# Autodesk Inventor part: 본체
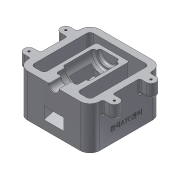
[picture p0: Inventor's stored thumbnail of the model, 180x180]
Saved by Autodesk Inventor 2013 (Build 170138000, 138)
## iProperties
Created: 2018-01
Part Number: 본체
Material: 알루미늄 6061
Document SubType Name: Modeling
Designer: Administrator
Density: 2.71 g/cm^3
Mass: 1089.46 g
Surface Area: 866.914 cm^2
Volume: 402.016 cm^3
Author: Administrator
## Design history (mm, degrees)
sketch "스케치2"
  geometry: L1 (-55, 55)-(55, 55); L2 (55, 55)-(55, -55); L3 (55, -55)-(-55, -55); L4 (-55, -55)-(-55, 55); L5 (-55, 55)-(55, -55); L6 (55, 55)-(-55, -55); 1 further point
  constraints: 12 end point, 2 midpoint, 2 parallel, 1 horizontal, 1 perpendicular
  dimensions: "d0" = 110 distance of L3.end L1.start; "d2" = 110 distance of L2.end L3.end
extrude "돌출1" new body sketch "스케치2" distance "d3" = 65; taper "d4" = 0 deg
fillet "모깎기1" dims "d5" = 15
sketch "스케치4"
  geometry: L1 (0, -55)-(0, 55) reference; L2 (0, 55)-(65, 55) reference; L3 (65, 55)-(65, -55) reference; L4 (65, -55)-(0, -55) reference; L5 (65, 55)-(57.5, 55); L6 (57.5, 55)-(57.5, 36); L7 (57.5, 36)-(49, 36); L8 (49, 36)-(49, 22); L9 (49, 22)-(45, 22); L10 (45, 22)-(45, -25); L11 (45, -25)-(50, -25); L12 (50, -25)-(50, -30); L13 (50, -30)-(65, -30); L14 (65, 55)-(65, -30); 1 further point
  constraints: 20 end point, 6 parallel, 2 perpendicular, 2 point on line, 1 collinear
  dimensions: "d9" = 15 diameter of L6 L3; "d10" = 32 diameter of L8 L3; "d11" = 40 diameter of L10 L3; "d12" = 30 diameter of L12 L3; "d31" = 19 distance between parallel lines of L7 L2; "d32" = 14 distance of L7.end L8.end; "d33" = 47 distance of L9.end L10.end; "d34" = 5 distance of L11.end L12.end
  node "절단 모서리 투영1"
revolve "회전1" stored, may be unused: angle "d13" = 90 deg
sketch "스케치6"
  geometry: L1 (-55, 40)-(-55, -40) reference; L2 (-40, -55)-(-7.5, -55) reference; L3 (-65, -20.5)-(-55, -20.5); L4 (-65, -35.5)-(-55, -35.5); L5 (-55, -35.5)-(-55, -20.5); A1 r 7.5 centre (-65, -28) between (-65, -20.5) and (-65, -35.5); 2 further points
  constraints: 6 end point, 2 perpendicular, 2 point on circle, 2 tangent, 1 centre point, 1 midpoint, 1 parallel, 1 point on line
  dimensions: "d16" = 7.5 radius of A1; "d18" = 10 distance from line of L1 A1.centre; "d19" = 27 distance from line of L2 A1.centre
extrude "돌출2" join sketch "스케치6" distance "d20" = 20; taper "d21" = 0 deg
hole "구멍1" diameter "d24" = 3.242; stored, may be unused: countersink angle "d28" = 90 deg, drill point angle "d30" = 118 deg; dims "d22" = 10, "d23" = 10, "d25" = 9, "d26" = 4, "d27" = 2, "d29" = 11
sketch "스케치8"
  geometry: L1 (0, -55)-(0, 55) reference; L2 (0, 55)-(57.5, 55) reference; L3 (57.5, 55)-(57.5, 36) reference; L4 (57.5, 36)-(49, 36) reference; L5 (49, 36)-(49, 22) reference; L6 (49, 22)-(45, 22) reference; L7 (45, 22)-(45, -25) reference; L8 (45, -25)-(50, -25) reference; L9 (50, -25)-(50, -30) reference; L10 (50, -30)-(65, -30) reference; L11 (65, -30)-(65, -55) reference; L12 (65, -55)-(0, -55) reference; L13 (40.135, 24.651)-(31.292, 55); L14 (13.292, 55)-(31.292, 55); L15 (65, -34.584)-(65, -45.371); L16 (13.292, 55)-(33.389, -20); L17 (33.389, -20)-(45, -20); L18 (40.135, 24.651)-(42.185, 17); L19 (42.185, 17)-(45, 17); L20 (45, 17)-(45, -20); 1 further point
  constraints: 16 end point, 6 point on line, 2 collinear, 2 perpendicular, 1 parallel
  dimensions: "d38" = 18 distance of L14.start L13.end; "d39" = 5 distance between parallel lines of L6 L19; "d40" = 5 distance between parallel lines of L8 L17
extrude "돌출3" cut sketch "스케치8" stored distance "d41" = 30; taper "d42" = 0 deg
sketch "스케치9"
  geometry: L1 (7.5, -55)-(40, -55) reference; L2 (40, 55)-(-40, 55) reference; L3 (-55, 20.5)-(-55, -20.5) reference; L4 (7.5, -55)-(7.5, -36) reference; L5 (7.5, -36)-(16, -36) reference; L6 (16, -36)-(16, -22) reference; L7 (16, -22)-(20, -22) reference; L8 (20, -22)-(20, 25) reference; L9 (20, 25)-(15, 25) reference; L10 (15, 25)-(15, 30) reference; L11 (15, 30)-(-15, 30) reference; L12 (-15, 30)-(-15, 25) reference; L13 (-15, 25)-(-20, 25) reference; L14 (-20, 25)-(-20, -22) reference; L15 (-20, -22)-(-16, -22) reference; L16 (-16, -22)-(-16, -36) reference; L17 (-16, -36)-(-7.5, -36) reference; L18 (-7.5, -36)-(-7.5, -55) reference; L19 (-7.5, -55)-(-40, -55) reference; L20 (-55, -40)-(-55, -35.5) reference; L21 (-55, -35.5)-(-65, -35.5) reference; L22 (-65, -20.5)-(-55, -20.5) reference; L23 (-55, -20.5)-(-55, 20.5) reference; L24 (-55, 20.5)-(-65, 20.5) reference; L25 (-65, 35.5)-(-55, 35.5) reference; L26 (-55, 35.5)-(-55, 40) reference; L27 (-40, 55)-(40, 55) reference; L28 (55, 40)-(55, 35.5) reference; L29 (55, 35.5)-(65, 35.5) reference; L30 (65, 20.5)-(55, 20.5) reference; L31 (55, 20.5)-(55, -20.5) reference; L32 (55, -20.5)-(65, -20.5) reference; L33 (65, -35.5)-(55, -35.5) reference; L34 (55, -35.5)-(55, -40) reference; L35 (40, -55)-(7.5, -55) reference; L36 (0, 55)-(0, 30); L37 (0, 35)-(-25, 35); L38 (-25, 35)-(-25, -45); L39 (-25, -45)-(-45, -45); L40 (-45, -45)-(-45, 45); L41 (-45, 45)-(0, 45); C1 r 1.621 at (65, 28) reference; C2 r 1.621 at (65, -28) reference; C3 r 1.621 at (-65, 28) reference; C4 r 1.621 at (-65, -28) reference; A1 r 15 centre (-40, -40) between (-55, -40) and (-40, -55) reference; A2 r 7.5 centre (-65, -28) between (-65, -20.5) and (-65, -35.5) reference; A3 r 7.5 centre (-65, 28) between (-65, 35.5) and (-65, 20.5) reference; A4 r 15 centre (-40, 40) between (-40, 55) and (-55, 40) reference; A5 r 15 centre (40, 40) between (55, 40) and (40, 55) reference; A6 r 7.5 centre (65, 28) between (65, 20.5) and (65, 35.5) reference; A7 r 7.5 centre (65, -28) between (65, -35.5) and (65, -20.5) reference; A8 r 15 centre (40, -40) between (40, -55) and (55, -40) reference; 1 further point
  constraints: 12 end point, 4 perpendicular, 2 midpoint, 2 point on line, 1 parallel, 1 vertical
  dimensions: "d43" = 10 distance between parallel lines of L3 L40; "d44" = 30 distance between parallel lines of L3 L38; "d45" = 10 distance between parallel lines of L2 L41; "d46" = 10 distance between parallel lines of L19 L39; "d47" = 20 distance between parallel lines of L2 L37
extrude "돌출4" cut sketch "스케치9" distance "d48" = 65; taper "d49" = 0 deg
sketch "스케치10"
  geometry: L1 (65, -45)-(65, -55) reference; L2 (65, -55)-(0, -55) reference; L3 (0, -55)-(0, -45) reference; L4 (0, -45)-(65, -45) reference; L5 (57.5, 55)-(57.5, 36) reference; L6 (57.5, 36)-(49, 36) reference; L7 (49, 36)-(49, 22) reference; L8 (49, 22)-(45, 22) reference; L9 (45, 22)-(45, 17) reference; L10 (45, 17)-(42.185, 17) reference; L11 (42.185, 17)-(40.135, 24.651) reference; L12 (40.135, 24.651)-(31.292, 55) reference; L13 (31.292, 55)-(57.5, 55) reference; L14 (45, -20)-(45, 17) reference; L15 (33.389, -20)-(45, -20) reference; L16 (13.292, 55)-(33.389, -20) reference; L17 (0, 55)-(13.292, 55) reference; L18 (0, -35)-(0, 55) reference; L19 (65, -35)-(0, -35) reference; L20 (65, -30)-(65, -35) reference; L21 (50, -30)-(65, -30) reference; L22 (50, -25)-(50, -30) reference; L23 (45, -25)-(50, -25) reference; L24 (45, -20)-(45, -25) reference; 1 further point
  node "절단 모서리 투영4"
node "작업 평면1"
sketch "스케치11"
  geometry: L1 (0, 45)-(8.564, 45); L2 (8.564, 45)-(30, -35); L3 (0, 45)-(0, -35) reference; L4 (0, -35)-(30, -35); L5 (0, -55)-(0, -40) reference; L6 (0, 55)-(65, 55) reference; 1 further point
  constraints: 6 end point, 1 horizontal, 1 perpendicular, 1 point on line
  dimensions: "d52" = 30 distance from line of L5 L2.end; "d53" = 105 deg angle of L2 L1; "d56" = 10 distance between parallel lines of L6 L1
extrude "돌출5" cut sketch "스케치11" distance "d54" = 20; taper "d55" = 0 deg
fillet "모깎기2" dims "d57" = 3
fillet "모깎기3" dims "d58" = 3
fillet "모깎기4" dims "d59" = 3
fillet "모깎기5" dims "d60" = 3
fillet "모깎기6" dims "d61" = 3
fillet "모깎기7" dims "d62" = 5
fillet "모깎기8" dims "d63" = 3
sketch "스케치12"
  geometry: L1 (-16, -22)-(-20, -22) reference; L2 (15, 0)-(-15, 0); L3 (-15, 0)-(-15, -17); L4 (-15, -17)-(15, -17); L5 (15, -17)-(15, 0); 2 further points
  constraints: 8 end point, 2 coincident, 2 parallel, 1 horizontal, 1 midpoint, 1 perpendicular
  dimensions: "d64" = 5 distance between parallel lines of L1 L4; "d65" = 30 distance of L2.start L2.end
extrude "돌출6" cut sketch "스케치12" stored distance "d66" = 20; taper "d67" = 0 deg
fillet "모깎기9" dims "d68" = 3
fillet "모깎기10" dims "d69" = 3
fillet "모깎기11" dims "d70" = 3
fillet "모깎기12" dims "d71" = 3
sketch "스케치13"
  geometry: L1 (80, 0)-(0, 0) reference; 3 further points
  constraints: 1 midpoint, 1 vertical alignment, 1 other
  dimensions: "d72" = 20 distance of point (40, 0) point (40, 20)
feature "엠보싱1" sketch "스케치13" dims "d74" = 0.5, "d75" = 0
chamfer "모따기1" distance "d76" = 1; stored, may be unused: second distance "d77" = 2, angle "d78" = 45 deg
node "솔리드1"
mirror "대칭1"
mirror "대칭2"
mirror "대칭3"
mirror "대칭4"
mirror "대칭5"
node "절단 모서리 투영2"
node "절단 모서리 투영3"
